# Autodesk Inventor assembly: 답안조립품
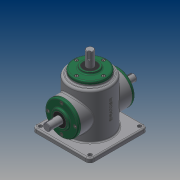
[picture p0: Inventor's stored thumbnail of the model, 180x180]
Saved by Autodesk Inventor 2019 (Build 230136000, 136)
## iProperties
Created: 2019-03
Part Number: 답안조립품
Material: 일반
Document SubType Name: Assembly
Designer: PC312-02
Author: PC312-02
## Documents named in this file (16)
- C:\Users\PC312-02\Desktop\490314V1013\답안조립품.iam
- C:\Users\PC312-02\Desktop\490314V1013\본체.ipt
- C:\Users\PC312-02\Desktop\490314V1013\커버.ipt
- C:\Users\PC312-02\Desktop\490314V1013\볼트 M4.ipt
- 볼트 M4.ipt
- C:\Users\PC312-02\Desktop\490314V1013\오일 실.ipt
- 오일 실.ipt
- C:\Users\PC312-02\Desktop\490314V1013\베어링 6203.ipt
- C:\Users\PC312-02\Desktop\490314V1013\메인 축.ipt
- 메인 축.ipt
- C:\Users\PC312-02\Desktop\490314V1013\키 5x5.ipt
- C:\Users\PC312-02\Desktop\490314V1013\메인 베벨기어.ipt
- C:\Users\PC312-02\Desktop\490314V1013\서브 축.ipt
- 서브 축.ipt
- C:\Users\PC312-02\Desktop\490314V1013\키 4x4.ipt
- C:\Users\PC312-02\Desktop\490314V1013\서브 베벨기어.ipt
